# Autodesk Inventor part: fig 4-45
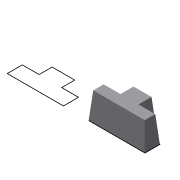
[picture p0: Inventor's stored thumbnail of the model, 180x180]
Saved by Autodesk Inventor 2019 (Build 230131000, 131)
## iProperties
Created: 2004-05
Part Number: fig 4-45
Document SubType Name: Modeling
Designer: CADCIM Technologies
Manufacturer: Standard
Standards Organization: Custom
Density: 1 g/cm^3
Material: Generic
Appearance: Default
Author: CADCIM Technologies
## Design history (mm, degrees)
sketch "Sketch1"
  geometry: L1 (31.783, 34.561)-(31.783, 22.933); L2 (31.783, 22.933)-(16.796, 22.933); L3 (16.796, 22.933)-(16.796, 9.496); L4 (16.796, 9.496)-(66.925, 9.496); L5 (66.925, 9.496)-(66.925, 22.933); L6 (66.925, 22.933)-(51.938, 22.933); L7 (51.938, 22.933)-(51.938, 34.561); L8 (51.938, 34.561)-(31.783, 34.561); L9 (-41.013, 34.561)-(-41.013, 22.933); L10 (-41.013, 22.933)-(-56, 22.933); L11 (-56, 22.933)-(-56, 9.496); L12 (-56, 9.496)-(-5.871, 9.496); L13 (-5.871, 9.496)-(-5.871, 22.933); L14 (-5.871, 22.933)-(-20.858, 22.933); L15 (-20.858, 22.933)-(-20.858, 34.561); L16 (-20.858, 34.561)-(-41.013, 34.561)
  constraints: 32 end point, 10 parallel, 4 equal length, 2 collinear, 2 perpendicular, 2 vertical
extrude "Extrusion1" new body sketch "Sketch1" distance "d0" = 23.25; taper "d1" = -5 deg
body "Solid1"
